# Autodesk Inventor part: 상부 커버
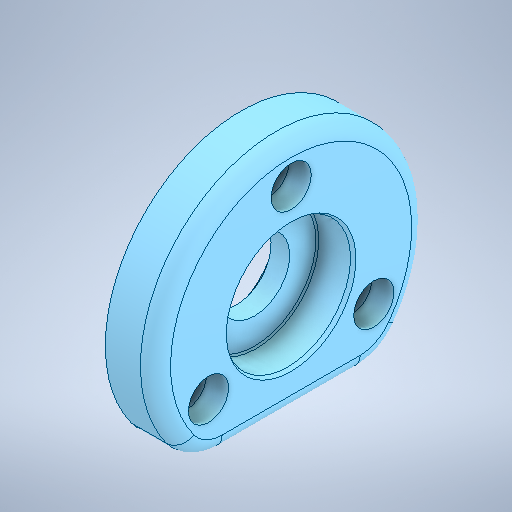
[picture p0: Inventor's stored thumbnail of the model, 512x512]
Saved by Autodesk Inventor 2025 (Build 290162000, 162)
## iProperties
Created: 2026-07
Part Number: 상부 커버
Material: 알루미늄 6061
Document SubType Name: Modeling
Designer: KDI
Density: 2.7 g/cm^3
Appearance: 알루미늄 - 평지
Mass: 46.1774 g
Surface Area: 69.3745 cm^2
Volume: 17.1027 cm^3
Sending System: Autodesk Inventor 2027
Preprocessor: ST-DEVELOPER v20.1
Author: jhkim
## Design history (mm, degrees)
feature "솔리드1"
node "솔리드2"
